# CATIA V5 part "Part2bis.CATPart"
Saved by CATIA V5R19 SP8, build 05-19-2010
Part number: Part2 encours
Bounding box of the stored display mesh (mm): x 0 to 100, y 0 to 600, z 0 to 155
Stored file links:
  G:\EU_thinkMotion\CFAO_2010\SIL_groupe2\SIL_groupe2\A reprendre\fnongaibaa\fnongaibaa\Part2bis.CATPart
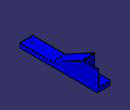
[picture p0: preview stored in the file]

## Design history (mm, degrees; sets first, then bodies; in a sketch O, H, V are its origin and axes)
Parameters
  `Longueur.1 A` = 0 mm
Body1 (main body)
  Sketch1 on yz-plane, origin (0, 0, 0), H (0, 1, 0), V (0, 0, 1)
    line L1 (0, 0) -> (0, 34)
    line L2 (0, 34) -> (250, 34)
    line L3 (250, 34) -> (475, 155)
    line L4 (0, 0) -> (600, 0)
    line L5 (600, 0) -> (600, 155)
    line L6 (600, 155) -> (475, 155)
    length L4 = 600
    length L1 = 34
    length L2 = 250
    length L6 = 125
    length L5 = 155
    vertical: L1 V, L5 V
    horizontal: L2 H, L4 H, L6 H
  Pad1: profile Sketch1, direction (1, 0, 0), length 100
  Sketch2 on face of Pad1 from Sketch1.L2, origin (16.1115, 28.9606, 34), H (1, 0, 0), V (0, 1, 0)
    point P1 (33.8885, 13.0394)
    axis line L1 (33.8885, 30) -> (33.8885, -60)
    reference projected line E1 (-16.1115, 53.571) -> (-16.1115, -28.9606) from edge [start face of Pad1 | face of Pad1 from Sketch1.L2]
    reference projected line E2 (83.8885, 53.571) -> (83.8885, -28.9606) from edge [face of Pad1 from Sketch1.L2 | end face of Pad1]
    reference projected line E3 (-16.1115, -28.9606) -> (3.8885, -28.9606) from edge [face of Pad1 from Sketch1.L1 | face of Pad1 from Sketch1.L2]
    distance P1 E3 = 42
    vertical: L1 V
    symmetry: E1 E2 L1
    coincidence: P1 L1
  Hole1: placed by Sketch2, at (50, 42, 34) direction (0, 0, -1), diameter 10, through (limit type 6)
  Sketch3 on start face of Pad1, origin (0, 0, 0), H (0, 1, 0), V (0, 0, 1)
    line L1 (600, 34) -> (480, 34)
    line L2 (480, 34) -> (480, 155)
    line L3 (480, 155) -> (600, 155)
    line L4 (600, 155) -> (600, 34)
    reference projected line E1 (600, 0) -> (600, 155) from edge [face of Pad1 from Sketch1.L5 | end face of Pad1]
    reference projected line E2 (600, 155) -> (475, 155) from edge [face of Pad1 from Sketch1.L6 | end face of Pad1]
    reference projected line E3 (250, 34) -> (0, 34) from edge [face of Pad1 from Sketch1.L2 | end face of Pad1]
    length L3 = 120
    horizontal: L1 H, L3 H
    vertical: L2 V, L4 V
    coincidence: E1 L4, L3 E2, E3 L1
  Pocket1: profile Sketch3, direction (1, 0, 0), length 90
  Sketch4 on face of Pocket1 from Sketch3.L1, origin (32.9224, 527.593, 34), H (1, 0, 0), V (0, 1, 0)
    point P1 (17.0776, 0.407)
    axis line L1 (17.0776, -130) -> (17.0776, 70)
    reference projected line E1 (67.0776, 72.407) -> (67.0776, -52.593) from edge [face of Pad1 from Sketch1.L6 | end face of Pad1]
    reference projected line E2 (-32.9224, -47.593) -> (-32.9224, 72.407) from edge [face of Pocket1 from Sketch3.L1 | start face of Pad1]
    reference projected line E3 (-32.9224, 72.407) -> (57.0776, 72.407) from edge [face of Pocket1 from Sketch3.L1 | face of Pad1 from Sketch1.L5]
    distance P1 E3 = 72
    vertical: L1 V
    symmetry: E1 E2 L1
    coincidence: P1 L1
  Hole2: placed by Sketch4, at (50, 528, 34) direction (0, 0, -1), diameter 10, through (limit type 6)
